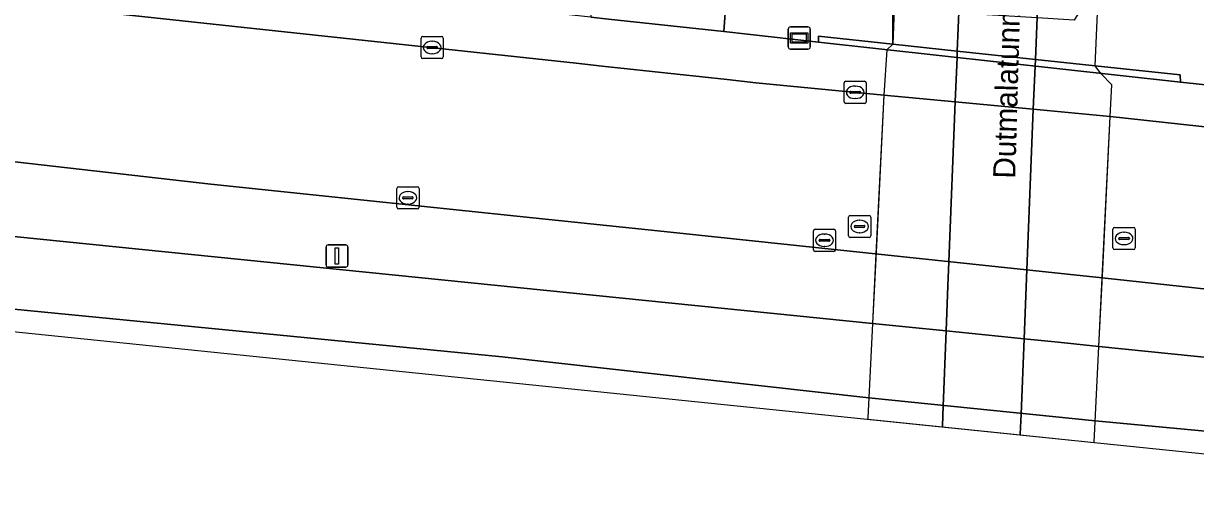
# Model space of a CAD drawing. Extents: x 161758 to 162722, y 384793 to 385405.
# Drawn here: x 162147.6 to 162200.5, y 384834 to 384855.3 of the extents above; entities that cross this region are included whole.
import ezdxf

# ---------------------------------------------------------------- set-up
doc = ezdxf.new("R2010")
doc.units = 0
for name, color, linetype in [('IMGEO_Berm_groen', 7, 'Continuous'), ('IMGEO_Fietspad_gesloten', 7, 'Continuous'), ('IMGEO_Groenvoorziening', 7, 'Continuous'), ('IMGEO_Kolk', 7, 'Continuous'), ('IMGEO_Lichtmast', 7, 'Continuous'), ('IMGEO_Muur', 7, 'Continuous'), ('IMGEO_Openbare_ruimte_label', 7, 'Continuous'), ('IMGEO_Rijbaan_lokaal_open', 7, 'Continuous'), ('IMGEO_Rijbaan_regionaal_gesloten', 7, 'Continuous'), ('IMGEO_Rioolput', 7, 'Continuous'), ('IMGEO_Tunneldeel', 7, 'Continuous'), ('IMGEO_Voetpad_open', 7, 'Continuous'), ('IMGEO_Wegwijzer', 7, 'Continuous')]:
    doc.layers.add(name, color=color, linetype=linetype)

msp = doc.modelspace()

# ---------------------------------------------------------------- linework, layer by layer
at = {"layer": 'IMGEO_Berm_groen'}
for points in [[(162196.294, 384843.825), (162176.537, 384845.917), (162169.888, 384846.605), (162156.076, 384848.057), (162140.223, 384849.851), (162121.361, 384851.862), (162121.052, 384848.339), (162185.929, 384841.772), (162187.436, 384841.619), (162189.251, 384841.435), (162192.767, 384841.08), (162194.3, 384840.925), (162196.141, 384840.739), (162261.713, 384834.101), (162291.726, 384830.473), (162298.135, 384829.505), (162306.89, 384828.091), (162315.827, 384826.441), (162321.473, 384825.346), (162350.99, 384818.894), (162380.078, 384810.862), (162402.695, 384803.51), (162404.257, 384805.879)], [(162266.874, 384836.344), (162253.954, 384837.702), (162246.186, 384838.478), (162238.742, 384839.348), (162233.995, 384839.83), (162225.879, 384840.718), (162220.098, 384841.298), (162216.103, 384841.703), (162204.623, 384842.922), (162196.294, 384843.825)]]:
    msp.add_lwpolyline(points, dxfattribs=at)
at = {"layer": 'IMGEO_Fietspad_gesloten'}
msp.add_lwpolyline([(162189.08, 384837.113), (162192.592, 384836.753), (162192.594, 384836.79), (162192.63, 384837.693), (162192.767, 384841.08), (162192.892, 384844.185), (162193.185, 384851.432), (162193.264, 384853.37), (162193.276, 384853.669), (162193.367, 384855.93), (162189.837, 384856.147), (162189.753, 384854.046), (162189.742, 384853.757), (162189.662, 384851.764), (162189.376, 384844.558), (162189.333, 384843.472), (162189.251, 384841.435), (162189.117, 384838.051), (162189.082, 384837.166)], close=True, dxfattribs=at)
at = {"layer": 'IMGEO_Groenvoorziening'}
for points in [[(162179.881, 384862.124), (162179.701, 384861.534), (162179.23, 384854.927), (162183.494, 384854.443), (162183.489, 384854.714), (162186.847, 384854.356), (162186.855, 384858.503), (162186.898, 384859.792), (162186.615, 384859.796), (162186.599, 384860.61), (162186.993, 384860.985), (162187.061, 384866.296)], [(162196.6, 384860.533), (162196.937, 384860.205), (162196.904, 384859.319), (162196.752, 384859.336), (162196.689, 384858.194), (162196.216, 384857.409), (162195.035, 384855.447), (162193.351, 384855.548), (162189.821, 384855.76), (162188.192, 384855.858), (162187.219, 384857.784), (162186.855, 384858.503), (162186.847, 384854.356), (162189.753, 384854.046), (162193.276, 384853.669), (162195.982, 384853.38), (162199.813, 384852.971), (162199.818, 384852.651), (162250.191, 384847.307)]]:
    msp.add_lwpolyline(points, dxfattribs=at)
at = {"layer": 'IMGEO_Kolk'}
for p, q in [((162165.564, 384853.784), (162165.564, 384854.636)), ((162165.639, 384854.71), (162166.491, 384854.71)), ((162166.052, 384854.49), (162166.077, 384854.49)), ((162166.565, 384854.636), (162166.565, 384853.784)), ((162165.823, 384854.204), (162165.823, 384854.216)), ((162166.261, 384854.167), (162165.863, 384854.167)), ((162165.866, 384854.253), (162166.264, 384854.253)), ((162166.075, 384853.93), (162166.05, 384853.93)), ((162166.307, 384854.216), (162166.307, 384854.204)), ((162166.491, 384853.71), (162165.639, 384853.71)), ((162184.649, 384851.764), (162184.649, 384852.616)), ((162184.724, 384852.69), (162185.576, 384852.69)), ((162185.137, 384852.47), (162185.162, 384852.47)), ((162185.65, 384852.616), (162185.65, 384851.764)), ((162184.908, 384852.184), (162184.908, 384852.196)), ((162185.346, 384852.147), (162184.948, 384852.147)), ((162184.951, 384852.233), (162185.349, 384852.233)), ((162185.16, 384851.91), (162185.135, 384851.91)), ((162185.392, 384852.196), (162185.392, 384852.184)), ((162185.576, 384851.69), (162184.724, 384851.69)), ((162164.47, 384847.009), (162164.47, 384847.861)), ((162164.545, 384847.935), (162165.397, 384847.935)), ((162164.958, 384847.715), (162164.983, 384847.715)), ((162165.471, 384847.861), (162165.471, 384847.009)), ((162164.729, 384847.429), (162164.729, 384847.441)), ((162165.167, 384847.392), (162164.769, 384847.392)), ((162164.772, 384847.478), (162165.17, 384847.478)), ((162164.981, 384847.155), (162164.956, 384847.155)), ((162165.213, 384847.441), (162165.213, 384847.429)), ((162165.397, 384846.935), (162164.545, 384846.935)), ((162183.336, 384846.022), (162184.188, 384846.022)), ((162183.261, 384845.096), (162183.261, 384845.948)), ((162183.52, 384845.516), (162183.52, 384845.528)), ((162183.958, 384845.479), (162183.56, 384845.479)), ((162183.563, 384845.565), (162183.961, 384845.565)), ((162183.749, 384845.802), (162183.774, 384845.802)), ((162184.004, 384845.528), (162184.004, 384845.516)), ((162184.262, 384845.948), (162184.262, 384845.096)), ((162184.188, 384845.022), (162183.336, 384845.022)), ((162183.772, 384845.242), (162183.747, 384845.242))]:
    msp.add_line(p, q, dxfattribs=at)
for points in [[(162165.564, 384853.784), (162165.564, 384854.636)], [(162165.639, 384854.71), (162166.491, 384854.71)], [(162166.565, 384854.636), (162166.565, 384853.784)], [(162166.491, 384853.71), (162165.639, 384853.71)], [(162184.649, 384851.764), (162184.649, 384852.616)], [(162184.724, 384852.69), (162185.576, 384852.69)], [(162185.65, 384852.616), (162185.65, 384851.764)], [(162185.576, 384851.69), (162184.724, 384851.69)], [(162164.47, 384847.009), (162164.47, 384847.861)], [(162164.545, 384847.935), (162165.397, 384847.935)], [(162165.471, 384847.861), (162165.471, 384847.009)], [(162165.397, 384846.935), (162164.545, 384846.935)], [(162183.336, 384846.022), (162184.188, 384846.022)], [(162183.261, 384845.096), (162183.261, 384845.948)], [(162184.262, 384845.948), (162184.262, 384845.096)], [(162184.188, 384845.022), (162183.336, 384845.022)]]:
    msp.add_lwpolyline(points, dxfattribs=at)
for centre, radius, start, end in [((162165.641, 384854.634), 0.0765, 91.552, 178.448), ((162165.641, 384854.634), 0.0765, 91.552, 178.448), ((162166.489, 384854.634), 0.0765, 1.552, 88.448), ((162166.489, 384854.634), 0.0765, 1.552, 88.448), ((162165.863, 384854.213), 0.0403, 85.8775, 175.7526), ((162165.86, 384854.203), 0.0366, 178.938, 274.7102), ((162166.264, 384854.21), 0.043, 264.8664, 352.4533), ((162166.268, 384854.215), 0.0386, 1.7309, 96.639), ((162165.641, 384853.786), 0.0765, 181.552, 268.448), ((162165.641, 384853.786), 0.0765, 181.552, 268.448), ((162166.489, 384853.786), 0.0765, 271.552, 358.448), ((162166.489, 384853.786), 0.0765, 271.552, 358.448), ((162184.726, 384852.614), 0.0765, 91.552, 178.448), ((162184.726, 384852.614), 0.0765, 91.552, 178.448), ((162185.574, 384852.614), 0.0765, 1.552, 88.448), ((162185.574, 384852.614), 0.0765, 1.552, 88.448), ((162184.948, 384852.193), 0.0403, 85.8775, 175.7526), ((162184.945, 384852.183), 0.0366, 178.938, 274.7102), ((162185.349, 384852.19), 0.043, 264.8664, 352.4533), ((162185.353, 384852.195), 0.0386, 1.7309, 96.639), ((162184.726, 384851.766), 0.0765, 181.552, 268.448), ((162184.726, 384851.766), 0.0765, 181.552, 268.448), ((162185.574, 384851.766), 0.0765, 271.552, 358.448), ((162185.574, 384851.766), 0.0765, 271.552, 358.448), ((162164.547, 384847.859), 0.0765, 91.552, 178.448), ((162164.547, 384847.859), 0.0765, 91.552, 178.448), ((162165.395, 384847.859), 0.0765, 1.552, 88.448), ((162165.395, 384847.859), 0.0765, 1.552, 88.448), ((162164.769, 384847.438), 0.0403, 85.8775, 175.7526), ((162164.766, 384847.428), 0.0366, 178.938, 274.7102), ((162165.17, 384847.435), 0.043, 264.8664, 352.4533), ((162165.174, 384847.44), 0.0386, 1.7309, 96.639), ((162164.547, 384847.011), 0.0765, 181.552, 268.448), ((162164.547, 384847.011), 0.0765, 181.552, 268.448), ((162165.395, 384847.011), 0.0765, 271.552, 358.448), ((162165.395, 384847.011), 0.0765, 271.552, 358.448), ((162183.338, 384845.946), 0.0765, 91.552, 178.448), ((162183.338, 384845.946), 0.0765, 91.552, 178.448), ((162184.186, 384845.946), 0.0765, 1.552, 88.448), ((162184.186, 384845.946), 0.0765, 1.552, 88.448), ((162183.56, 384845.525), 0.0403, 85.8775, 175.7526), ((162183.557, 384845.515), 0.0366, 178.938, 274.7102), ((162183.961, 384845.522), 0.043, 264.8664, 352.4533), ((162183.965, 384845.527), 0.0386, 1.7309, 96.639), ((162183.338, 384845.098), 0.0765, 181.552, 268.448), ((162183.338, 384845.098), 0.0765, 181.552, 268.448), ((162184.186, 384845.098), 0.0765, 271.552, 358.448), ((162184.186, 384845.098), 0.0765, 271.552, 358.448)]:
    msp.add_arc(centre, radius, start, end, dxfattribs=at)
for centre, major_axis, ratio, start_param, end_param in [((162166.051, 384854.21), (-0.387, 0.002), 0.722429, 4.712389, 7.853982), ((162166.076, 384854.21), (-0.39, 0.002), 0.717154, 1.570796, 4.712389), ((162185.136, 384852.19), (-0.387, 0.002), 0.722429, 4.712389, 7.853982), ((162185.161, 384852.19), (-0.39, 0.002), 0.717154, 1.570796, 4.712389), ((162164.957, 384847.435), (-0.387, 0.002), 0.722429, 4.712389, 7.853982), ((162164.982, 384847.435), (-0.39, 0.002), 0.717154, 1.570796, 4.712389), ((162183.748, 384845.522), (-0.387, 0.002), 0.722429, 4.712389, 7.853982), ((162183.773, 384845.522), (-0.39, 0.002), 0.717154, 1.570796, 4.712389)]:
    msp.add_ellipse(centre, major_axis=major_axis, ratio=ratio, start_param=start_param, end_param=end_param, dxfattribs=at)
at = {"layer": 'IMGEO_Lichtmast'}
for p, q in [((162161.275, 384844.415), (162161.275, 384845.215)), ((162161.275, 384845.215), (162161.275, 384844.415)), ((162161.375, 384845.315), (162162.165, 384845.315)), ((162162.165, 384845.315), (162161.375, 384845.315)), ((162162.265, 384845.215), (162162.265, 384844.415)), ((162162.265, 384844.415), (162162.265, 384845.215)), ((162162.165, 384844.315), (162161.375, 384844.315)), ((162161.375, 384844.315), (162162.165, 384844.315))]:
    msp.add_line(p, q, dxfattribs=at)
msp.add_lwpolyline([(162161.695, 384845.19), (162161.845, 384845.19), (162161.845, 384844.44), (162161.695, 384844.44), (162161.695, 384845.19)], dxfattribs=at)
for centre, start, end in [((162161.375, 384845.215), 90, 180), ((162161.375, 384845.215), 90, 180), ((162162.165, 384845.215), 0, 90), ((162162.165, 384845.215), 360, 90), ((162161.375, 384844.415), 180, 270), ((162161.375, 384844.415), 180, 270), ((162162.165, 384844.415), 270, 0), ((162162.165, 384844.415), 270, 0)]:
    msp.add_arc(centre, 0.1, start, end, dxfattribs=at)
at = {"layer": 'IMGEO_Muur'}
msp.add_lwpolyline([(162186.847, 384854.356), (162183.489, 384854.714), (162183.494, 384854.443), (162199.818, 384852.651), (162199.813, 384852.971), (162195.982, 384853.38), (162193.276, 384853.669), (162189.753, 384854.046)], close=True, dxfattribs=at)
at = {"layer": 'IMGEO_Rijbaan_lokaal_open'}
for points in [[(162173.808, 384863.498), (162173.216, 384855.57), (162174.012, 384855.484), (162179.23, 384854.927), (162179.701, 384861.534), (162179.881, 384862.124), (162178.605, 384866.47)], [(162065.033, 384857.642), (162072.258, 384856.957), (162097.628, 384854.37), (162105.852, 384853.479), (162103.299, 384850.228), (162108.896, 384849.572), (162109.342, 384850.113), (162114.246, 384852.545), (162120.024, 384851.99), (162121.361, 384851.862), (162140.223, 384849.851), (162156.076, 384848.057), (162169.888, 384846.605), (162176.537, 384845.917), (162196.294, 384843.825), (162204.623, 384842.922), (162216.103, 384841.703), (162220.098, 384841.298), (162225.879, 384840.718), (162233.995, 384839.83), (162238.742, 384839.348), (162246.186, 384838.478), (162253.954, 384837.702), (162266.874, 384836.344)], [(162196.657, 384851.104), (162193.185, 384851.432), (162189.662, 384851.764), (162186.438, 384852.069), (162180.669, 384852.613), (162179.371, 384852.762), (162173.734, 384853.372), (162172.558, 384853.51), (162145.258, 384856.454), (162132.687, 384857.788)], [(162336.349, 384832.447), (162327.195, 384834.339), (162316.831, 384836.287), (162288.799, 384840.797), (162274.417, 384842.694), (162259.864, 384844.251), (162248.91, 384845.406), (162196.657, 384851.104)]]:
    msp.add_lwpolyline(points, dxfattribs=at)
at = {"layer": 'IMGEO_Rijbaan_regionaal_gesloten'}
for points in [[(162261.713, 384834.101), (162196.141, 384840.739), (162194.3, 384840.925), (162192.767, 384841.08), (162189.251, 384841.435), (162187.436, 384841.619), (162185.929, 384841.772), (162121.052, 384848.339), (162119.641, 384848.482), (162113.861, 384849.068), (162108.896, 384849.572), (162103.299, 384850.228), (162098.216, 384850.795), (162045.97, 384856.082), (162017.318, 384858.792), (161968.205, 384864.005), (161935.339, 384867.25), (161900.935, 384869.807)], [(161914.995, 384864.529), (161989.003, 384857.616), (162108.003, 384845.421), (162200.922, 384835.899)], [(161930.324, 384864.521), (161942.922, 384863.321), (161970.016, 384860.621), (162005.209, 384856.921), (162044.901, 384852.969), (162091.94, 384848.018), (162120.626, 384845.08), (162133.931, 384843.718), (162169.223, 384840.267), (162185.764, 384838.425), (162195.974, 384837.38), (162214.263, 384835.667)], [(162214.263, 384835.667), (162195.974, 384837.38), (162185.764, 384838.425), (162169.223, 384840.267), (162133.931, 384843.718), (162120.626, 384845.08), (162091.94, 384848.018), (162044.901, 384852.969), (162005.209, 384856.921), (161970.016, 384860.621), (161942.922, 384863.321), (161930.324, 384864.521)]]:
    msp.add_lwpolyline(points, dxfattribs=at)
at = {"layer": 'IMGEO_Rioolput'}
for p, q in [((162184.848, 384845.718), (162184.848, 384846.57)), ((162184.923, 384846.644), (162185.775, 384846.644)), ((162185.849, 384846.57), (162185.849, 384845.718)), ((162185.107, 384846.138), (162185.107, 384846.15)), ((162185.545, 384846.101), (162185.147, 384846.101)), ((162185.15, 384846.187), (162185.548, 384846.187)), ((162185.336, 384846.424), (162185.361, 384846.424)), ((162185.591, 384846.15), (162185.591, 384846.138)), ((162196.778, 384845.179), (162196.778, 384846.031)), ((162196.853, 384846.105), (162197.705, 384846.105)), ((162197.779, 384846.031), (162197.779, 384845.179)), ((162185.775, 384845.644), (162184.923, 384845.644)), ((162185.359, 384845.864), (162185.334, 384845.864)), ((162197.037, 384845.599), (162197.037, 384845.611)), ((162197.475, 384845.562), (162197.077, 384845.562)), ((162197.08, 384845.648), (162197.478, 384845.648)), ((162197.266, 384845.885), (162197.291, 384845.885)), ((162197.521, 384845.611), (162197.521, 384845.599)), ((162197.705, 384845.105), (162196.853, 384845.105)), ((162197.289, 384845.325), (162197.264, 384845.325))]:
    msp.add_line(p, q, dxfattribs=at)
for points in [[(162184.848, 384845.718), (162184.848, 384846.57)], [(162184.923, 384846.644), (162185.775, 384846.644)], [(162185.849, 384846.57), (162185.849, 384845.718)], [(162196.778, 384845.179), (162196.778, 384846.031)], [(162196.853, 384846.105), (162197.705, 384846.105)], [(162197.779, 384846.031), (162197.779, 384845.179)], [(162185.775, 384845.644), (162184.923, 384845.644)], [(162197.705, 384845.105), (162196.853, 384845.105)]]:
    msp.add_lwpolyline(points, dxfattribs=at)
for centre, radius, start, end in [((162184.925, 384846.568), 0.0765, 91.552, 178.448), ((162184.925, 384846.568), 0.0765, 91.552, 178.448), ((162185.773, 384846.568), 0.0765, 1.552, 88.448), ((162185.773, 384846.568), 0.0765, 1.552, 88.448), ((162185.147, 384846.147), 0.0403, 85.8775, 175.7526), ((162185.144, 384846.137), 0.0366, 178.938, 274.7102), ((162185.548, 384846.144), 0.043, 264.8664, 352.4533), ((162185.552, 384846.149), 0.0386, 1.7309, 96.639), ((162196.855, 384846.029), 0.0765, 91.552, 178.448), ((162196.855, 384846.029), 0.0765, 91.552, 178.448), ((162197.703, 384846.029), 0.0765, 1.552, 88.448), ((162197.703, 384846.029), 0.0765, 1.552, 88.448), ((162184.925, 384845.72), 0.0765, 181.552, 268.448), ((162184.925, 384845.72), 0.0765, 181.552, 268.448), ((162185.773, 384845.72), 0.0765, 271.552, 358.448), ((162185.773, 384845.72), 0.0765, 271.552, 358.448), ((162197.077, 384845.608), 0.0403, 85.8775, 175.7526), ((162197.074, 384845.598), 0.0366, 178.938, 274.7102), ((162197.478, 384845.605), 0.043, 264.8664, 352.4533), ((162197.482, 384845.61), 0.0386, 1.7309, 96.639), ((162196.855, 384845.181), 0.0765, 181.552, 268.448), ((162196.855, 384845.181), 0.0765, 181.552, 268.448), ((162197.703, 384845.181), 0.0765, 271.552, 358.448), ((162197.703, 384845.181), 0.0765, 271.552, 358.448)]:
    msp.add_arc(centre, radius, start, end, dxfattribs=at)
for centre, major_axis, ratio, start_param, end_param in [((162185.335, 384846.144), (-0.387, 0.002), 0.722429, 4.712389, 7.853982), ((162185.36, 384846.144), (-0.39, 0.002), 0.717154, 1.570796, 4.712389), ((162197.265, 384845.605), (-0.387, 0.002), 0.722429, 4.712389, 7.853982), ((162197.29, 384845.605), (-0.39, 0.002), 0.717154, 1.570796, 4.712389)]:
    msp.add_ellipse(centre, major_axis=major_axis, ratio=ratio, start_param=start_param, end_param=end_param, dxfattribs=at)
at = {"layer": 'IMGEO_Tunneldeel'}
msp.add_lwpolyline([(162195.926, 384836.411), (162195.927, 384836.433), (162196.141, 384840.739), (162196.314, 384844.227), (162196.657, 384851.104), (162196.725, 384852.521), (162196.225, 384853.045), (162195.982, 384853.38), (162196.077, 384855.765), (162196.267, 384858.28), (162194.814, 384855.842), (162193.367, 384855.93), (162189.837, 384856.147), (162188.44, 384856.232), (162187.261, 384858.627), (162186.926, 384856.324), (162186.847, 384854.356), (162186.581, 384854.104), (162186.438, 384852.069), (162186.103, 384845.281), (162185.929, 384841.772), (162185.719, 384837.526), (162185.716, 384837.457)], close=True, dxfattribs=at)
at = {"layer": 'IMGEO_Voetpad_open'}
for points in [[(162199.818, 384852.651), (162183.494, 384854.443), (162179.23, 384854.927), (162174.012, 384855.484), (162173.216, 384855.57), (162131.027, 384860.111), (162126.138, 384860.491)], [(162132.687, 384857.788), (162145.258, 384856.454), (162172.558, 384853.51), (162173.734, 384853.372), (162179.371, 384852.762), (162180.669, 384852.613), (162186.438, 384852.069), (162189.662, 384851.764), (162193.185, 384851.432), (162196.657, 384851.104), (162248.91, 384845.406), (162248.991, 384846.134), (162260.001, 384844.996), (162259.864, 384844.251), (162274.417, 384842.694), (162288.799, 384840.797), (162316.831, 384836.287), (162327.195, 384834.339), (162336.349, 384832.447)], [(162408.323, 384812.045), (162409.676, 384814.097), (162394.807, 384818.82), (162368.573, 384826.736), (162355.529, 384830.108), (162344.315, 384832.787), (162342.336, 384833.244), (162322.861, 384837.358), (162275.019, 384844.76), (162259.423, 384846.371), (162257.607, 384846.559), (162257.064, 384846.615), (162250.932, 384847.228), (162250.191, 384847.307), (162199.818, 384852.651)]]:
    msp.add_lwpolyline(points, dxfattribs=at)
for points in [[(162185.716, 384837.457), (162189.08, 384837.113), (162189.082, 384837.166), (162189.117, 384838.051), (162189.251, 384841.435), (162189.333, 384843.472), (162189.376, 384844.558), (162189.662, 384851.764), (162189.742, 384853.757), (162189.753, 384854.046), (162189.837, 384856.147), (162188.44, 384856.232), (162187.261, 384858.627), (162186.926, 384856.324), (162186.847, 384854.356), (162186.581, 384854.104), (162186.438, 384852.069), (162186.084, 384844.906), (162185.929, 384841.772), (162185.719, 384837.526)], [(162192.592, 384836.753), (162195.926, 384836.411), (162195.927, 384836.433), (162196.141, 384840.739), (162196.294, 384843.825), (162196.657, 384851.104), (162196.725, 384852.521), (162196.225, 384853.045), (162195.982, 384853.38), (162196.077, 384855.765), (162196.267, 384858.28), (162194.814, 384855.842), (162193.367, 384855.93), (162193.276, 384853.669), (162193.264, 384853.37), (162193.185, 384851.432), (162192.892, 384844.185), (162192.767, 384841.08), (162192.63, 384837.693), (162192.594, 384836.79)]]:
    msp.add_lwpolyline(points, close=True, dxfattribs=at)
at = {"layer": 'IMGEO_Wegwijzer'}
for p, q in [((162182.128, 384854.239), (162182.128, 384855.039)), ((162182.128, 384855.039), (162182.128, 384854.239)), ((162182.228, 384855.139), (162183.018, 384855.139)), ((162183.018, 384855.139), (162182.228, 384855.139)), ((162183.118, 384855.039), (162183.118, 384854.239)), ((162183.118, 384854.239), (162183.118, 384855.039)), ((162183.018, 384854.139), (162182.228, 384854.139)), ((162182.228, 384854.139), (162183.018, 384854.139))]:
    msp.add_line(p, q, dxfattribs=at)
for points in [[(162182.229, 384854.871), (162183.017, 384854.871), (162183.017, 384854.407), (162182.229, 384854.407), (162182.229, 384854.871)], [(162182.294, 384854.806), (162182.294, 384854.472), (162182.952, 384854.472), (162182.952, 384854.806), (162182.294, 384854.806)]]:
    msp.add_lwpolyline(points, dxfattribs=at)
for centre, start, end in [((162182.228, 384855.039), 90, 180), ((162182.228, 384855.039), 90, 180), ((162183.018, 384855.039), 0, 90), ((162183.018, 384855.039), 360, 90), ((162182.228, 384854.239), 180, 270), ((162182.228, 384854.239), 180, 270), ((162183.018, 384854.239), 270, 0), ((162183.018, 384854.239), 270, 0)]:
    msp.add_arc(centre, 0.1, start, end, dxfattribs=at)

# ---------------------------------------------------------------- texts
at = {"layer": 'IMGEO_Openbare_ruimte_label'}
msp.add_text('Dutmalatunnel', height=1, rotation=88.3389, dxfattribs=at).set_placement((162192.367, 384848.29))

doc.saveas('drawing.dxf')
